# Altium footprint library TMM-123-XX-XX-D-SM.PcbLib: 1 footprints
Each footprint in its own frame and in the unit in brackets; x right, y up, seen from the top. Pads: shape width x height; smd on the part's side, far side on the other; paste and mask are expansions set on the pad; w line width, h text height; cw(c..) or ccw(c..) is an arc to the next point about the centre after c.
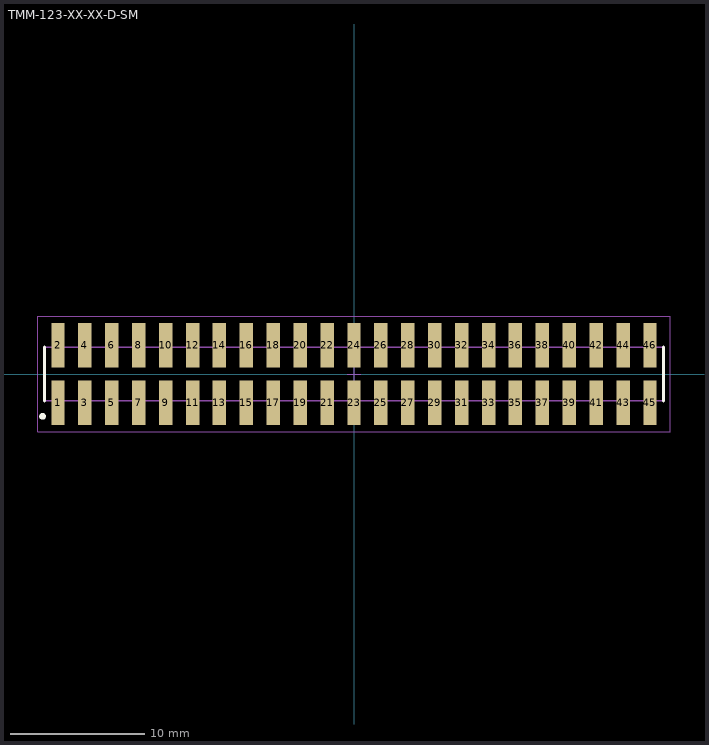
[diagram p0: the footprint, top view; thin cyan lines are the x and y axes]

## TMM-123-XX-XX-D-SM [mm] "2.00mm pitch, 46 pin, terminal strip; double row, SMT"
height 2.77
pads (46):
  rect 1x3.3 smd mask+0: 1(-22,-2.15) 2(-22,2.15) 3(-20,-2.15) 4(-20,2.15) 5(-18,-2.15) 6(-18,2.15) 7(-16,-2.15) 8(-16,2.15) 9(-14,-2.15) 10(-14,2.15) 11(-12,-2.15) 12(-12,2.15) 13(-10,-2.15) 14(-10,2.15) 15(-8,-2.15) 16(-8,2.15) 17(-6,-2.15) 18(-6,2.15) 19(-4,-2.15) 20(-4,2.15) 21(-2,-2.15) 22(-2,2.15) 23(0,-2.15) 24(0,2.15) 25(2,-2.15) 26(2,2.15) 27(4,-2.15) 28(4,2.15) 29(6,-2.15) 30(6,2.15) 31(8,-2.15) 32(8,2.15) 33(10,-2.15) 34(10,2.15) 35(12,-2.15) 36(12,2.15) 37(14,-2.15) 38(14,2.15) 39(16,-2.15) 40(16,2.15) 41(18,-2.15) 42(18,2.15) 43(20,-2.15) 44(20,2.15) 45(22,-2.15) 46(22,2.15)
Top Overlay:
  circle w0.25: c-23.15,-3.15 r0.125
  lines w0.2: -23,-2 -23,2 ; 23,-2 23,2
Mechanical 12:
  lines w0.001: -23,-2 -23,2 23,2 23,-2 -23,-2
Mechanical 13:
  lines w0.1: -23,-2 -23,2 23,2 23,-2 -23,-2
  text ".Designator" at 0,-0.127 h1.52
Mechanical 15:
  lines w0.05: -0.5,0 0.5,0 ; 0,-0.5 0,0.5 ; -23.5,-4.3 -23.5,4.3 23.5,4.3 23.5,-4.3 -23.5,-4.3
